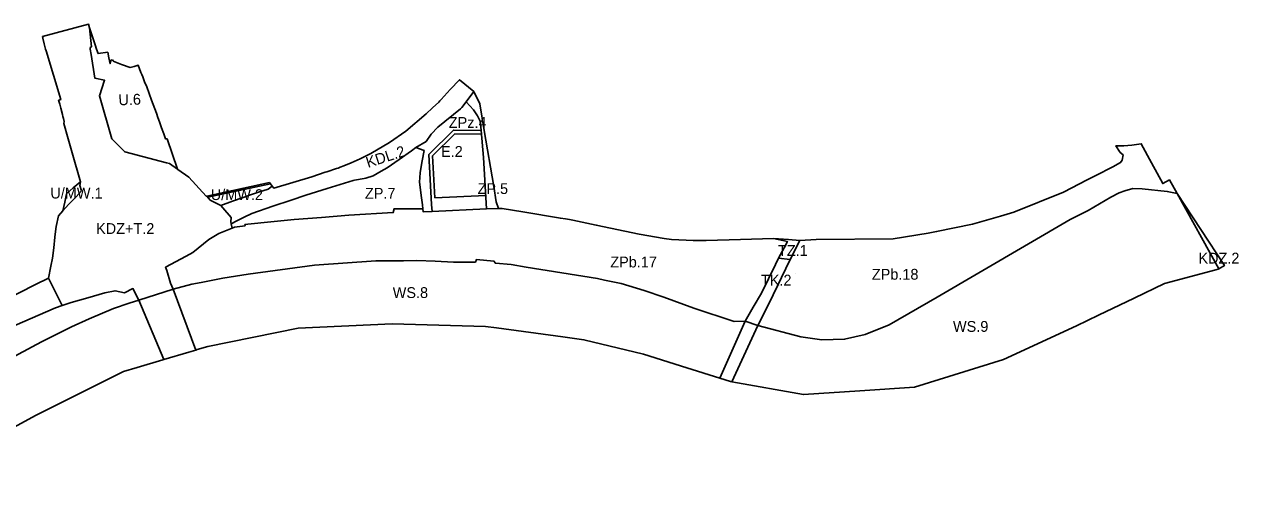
# Model space of a CAD drawing. Extents: x 7421697 to 7426767, y 5545731 to 5547485.
# Drawn here: x 7425420 to 7426767, y 5546623 to 5547146 of the extents above; entities that cross this region are included whole.
import ezdxf

# ---------------------------------------------------------------- set-up
doc = ezdxf.new("R2010")
doc.units = 0
for name, color, linetype in [('LIN_Linia Zabudowy Nieprzekraczalna', 7, 'Continuous'), ('LIN_linie rozgraniczające terenu WS', 7, 'Continuous'), ('LIN_linie_rozgraniczajace', 7, 'Continuous'), ('TXT_oznaczenia_przeznaczen', 7, 'Continuous')]:
    doc.layers.add(name, color=color, linetype=linetype)

msp = doc.modelspace()

# ---------------------------------------------------------------- linework, layer by layer
at = {"layer": 'LIN_Linia Zabudowy Nieprzekraczalna'}
for p, q in [((7425623.5, 5546954.6), (7425693.1, 5546969.4)), ((7425875.5, 5546953.9), (7425931.9, 5546956.6))]:
    msp.add_line(p, q, dxfattribs=at)
for points in [[(7425926.9, 5547024.5), (7425897.7, 5547025.1), (7425872.8, 5547000.4)], [(7425872.8, 5547000.4), (7425875.5, 5546953.9)]]:
    msp.add_lwpolyline(points, dxfattribs=at)
at = {"layer": 'LIN_linie rozgraniczające terenu WS'}
for p, q in [((7425585.1, 5546852.7), (7425547.1, 5546840.6)), ((7426233.8, 5546812.6), (7426219.6, 5546817.2))]:
    msp.add_line(p, q, dxfattribs=at)
at = {"layer": 'LIN_linie_rozgraniczajace'}
for p, q in [((7425929.5, 5546998.7), (7425927, 5547028.5)), ((7425854.4, 5547009.9), (7425863.7, 5547006.3)), ((7425481.8, 5546967.8), (7425482.3, 5546971.6)), ((7426745.1, 5546875.3), (7426698.6, 5546958.8)), ((7426256.7, 5546886.9), (7426269.7, 5546885.5)), ((7425446.8, 5546864.8), (7425462.3, 5546834.6)), ((7425574.9, 5546774.7), (7425547.1, 5546840.6)), ((7426219.6, 5546817.2), (7426191.5, 5546754)), ((7426233.8, 5546812.6), (7426205, 5546749.9))]:
    msp.add_line(p, q, dxfattribs=at)
for points in [[(7425395.5, 5546839), (7425432.7, 5546857.7), (7425446.8, 5546864.8), (7425449.6, 5546878.2), (7425451.5, 5546887.1), (7425452.7, 5546898.6), (7425454, 5546910.5), (7425455, 5546919.7), (7425455.5, 5546922), (7425457.9, 5546933.9), (7425462.7, 5546939.4), (7425464.9, 5546949.3), (7425466.8, 5546958.3), (7425474.5, 5546965), (7425482.3, 5546971.6), (7425473.1, 5547004), (7425468.7, 5547019.4), (7425463.9, 5547036.5), (7425464.4, 5547038.7), (7425463.5, 5547041.9), (7425462.9, 5547044.1), (7425462.4, 5547046.3), (7425460.8, 5547053.4), (7425459.5, 5547057.8), (7425458.2, 5547062.1), (7425459.4, 5547062.5), (7425460.6, 5547062.8), (7425452.4, 5547089.9), (7425444.3, 5547116.9), (7425443.8, 5547118.9), (7425442.3, 5547124.8), (7425440.8, 5547130.8), (7425440.6, 5547131.8), (7425440.3, 5547132.9), (7425491.4, 5547146.4), (7425492.6, 5547142.6), (7425498.8, 5547123.4), (7425500.3, 5547118.8), (7425501.9, 5547113.8), (7425512.7, 5547115.4), (7425514, 5547109.1), (7425515.2, 5547102.7), (7425515.9, 5547104.8), (7425516.6, 5547106.8), (7425519, 5547106.1), (7425518.8, 5547105.5), (7425528, 5547101.6), (7425537.4, 5547098.3), (7425541.9, 5547099.6), (7425546.5, 5547101), (7425548, 5547097), (7425549.5, 5547093), (7425550.4, 5547090.6), (7425551.4, 5547088.2), (7425553.6, 5547082.6), (7425555.9, 5547076.9), (7425561.2, 5547062.4), (7425566.6, 5547047.9), (7425568.2, 5547043.1), (7425569.9, 5547038.4), (7425572.2, 5547031.6), (7425574.7, 5547024.8), (7425576.7, 5547019.4), (7425578.5, 5547019.2), (7425590.1, 5546985.9), (7425590.3, 5546985.2), (7425602.5, 5546977), (7425621.9, 5546955.7), (7425622.4, 5546955.8), (7425691.9, 5546970.8), (7425695.1, 5546966.9), (7425697, 5546964.6), (7425739.2, 5546977.4), (7425753.7, 5546982.3), (7425755.7, 5546982.9), (7425766.3, 5546986.3), (7425768.4, 5546987), (7425770.5, 5546987.8), (7425774.6, 5546989.3), (7425782.7, 5546992.6), (7425792.6, 5546997.2), (7425804.3, 5547003.1), (7425825.1, 5547015.3), (7425843.1, 5547027.9), (7425866, 5547047), (7425872.8, 5547053.6), (7425879.7, 5547060.2), (7425881, 5547061.6), (7425882.3, 5547063), (7425892.5, 5547074), (7425902.8, 5547084.9), (7425918.6, 5547072), (7425925.3, 5547058.1), (7425930.3, 5547028.5), (7425940.7, 5546966.7), (7425943.6, 5546949.5), (7425945.9, 5546942.3), (7425950, 5546942), (7425972.9, 5546938.4), (7426014.8, 5546931.3), (7426020.2, 5546930.6), (7426024.8, 5546929.9), (7426028.5, 5546929.2), (7426054.5, 5546923.8), (7426102.1, 5546913.6), (7426129.8, 5546908.8), (7426138.1, 5546907.8), (7426154.2, 5546907), (7426162.1, 5546906.7), (7426176.2, 5546906.8), (7426214.4, 5546907.8), (7426251.2, 5546908.7), (7426267.7, 5546907.6), (7426280.4, 5546906.8), (7426298.2, 5546907.8), (7426383.7, 5546908.5), (7426422.5, 5546914.8), (7426432, 5546916.5), (7426471.8, 5546924.7), (7426502.7, 5546933.5), (7426517.6, 5546938.1), (7426572.7, 5546960.2), (7426599, 5546973.9), (7426608.7, 5546978.9), (7426627.5, 5546988.4), (7426635.9, 5546993.1), (7426637.6, 5546995.9), (7426638.7, 5547001.5), (7426635.6, 5547004.4), (7426630.8, 5547011.7), (7426636.1, 5547011.6), (7426639.5, 5547011.5), (7426648.5, 5547012.4), (7426658.9, 5547014), (7426670.2, 5546992.7), (7426682.8, 5546969.8), (7426690.1, 5546973.9), (7426698.6, 5546958.8), (7426751.2, 5546878.9), (7426745.1, 5546875.3), (7426744.2, 5546874.7), (7426741.8, 5546874.1), (7426684.8, 5546858.9), (7426651.2, 5546842.7), (7426611.5, 5546823.9), (7426587, 5546812.2), (7426506.2, 5546774.8), (7426407.3, 5546744), (7426346.9, 5546740), (7426284.3, 5546735.8), (7426205, 5546749.9), (7426203.3, 5546750.2), (7426191.5, 5546754), (7426155.1, 5546765.4), (7426106.9, 5546780.6), (7426040.7, 5546796.6), (7426017.4, 5546799.8), (7425943.8, 5546809.7), (7425931.6, 5546811.4), (7425828.1, 5546814.3), (7425724, 5546809.4), (7425623.7, 5546789.1), (7425612, 5546785.7), (7425610.2, 5546785.1), (7425602.7, 5546782.9), (7425574.9, 5546774.7), (7425573.9, 5546774.4), (7425545.3, 5546765.9), (7425530.3, 5546761.5), (7425432.4, 5546712.6), (7425356.2, 5546671.4)], [(7425517.2, 5547019.3), (7425503.4, 5547067.2), (7425509.1, 5547084.3), (7425498.3, 5547086.8), (7425494.3, 5547112.7), (7425493.3, 5547118.8), (7425493.1, 5547120.5), (7425494.8, 5547121.4), (7425492.6, 5547142.6)], [(7425854.4, 5547009.9), (7425865.7, 5547016.6), (7425871.2, 5547024.5), (7425878.6, 5547032.2), (7425903.8, 5547052.8), (7425905.4, 5547054.1), (7425910.1, 5547060.4), (7425918.6, 5547072)], [(7425910.1, 5547060.4), (7425918.5, 5547051.4), (7425922.8, 5547044.8), (7425925.6, 5547039.1), (7425926.6, 5547032.8), (7425927, 5547028.5)], [(7425868.7, 5547002), (7425896.1, 5547029.1), (7425927, 5547028.5)], [(7425590.1, 5546985.9), (7425581, 5546992.1), (7425577.8, 5546992.9), (7425531.5, 5547004.9), (7425517.2, 5547019.3)], [(7425786.3, 5546973.4), (7425797, 5546975.5), (7425798.8, 5546975.9), (7425807.1, 5546978.2), (7425815.9, 5546983.4), (7425822.4, 5546987.2), (7425836, 5546996.6), (7425849.7, 5547006.1), (7425854.4, 5547009.9)], [(7425863.7, 5547006.3), (7425861.5, 5546994.9), (7425859.2, 5546982), (7425858.9, 5546976.2), (7425858.6, 5546971.8), (7425860.4, 5546956.7), (7425861.6, 5546946.1), (7425862.1, 5546941.6)], [(7425868.7, 5547002), (7425871.9, 5546946.5), (7425872.4, 5546938.9)], [(7425929.5, 5546998.7), (7425932.7, 5546941.7)], [(7425649.5, 5546925.3), (7425655.7, 5546928.6), (7425664, 5546932.7), (7425672.6, 5546936.5), (7425695.7, 5546944.6), (7425716.2, 5546951.2), (7425732.5, 5546957), (7425756, 5546964.3), (7425784.9, 5546973.1), (7425786.3, 5546973.4)], [(7425483.4, 5546961.6), (7425477.5, 5546955.2), (7425469, 5546946.6), (7425462.7, 5546939.4)], [(7425481.8, 5546967.8), (7425483.4, 5546961.6)], [(7425638.1, 5546945.3), (7425651.2, 5546950.2), (7425663, 5546954.5), (7425671.1, 5546957.4), (7425678.9, 5546959.7), (7425690.6, 5546963.6), (7425695.1, 5546966.9)], [(7426698.6, 5546958.8), (7426687.7, 5546961), (7426660, 5546964), (7426649.7, 5546964.4), (7426640.6, 5546961.8), (7426634.6, 5546959.4), (7426625.3, 5546954.8), (7426599.9, 5546939.9), (7426579.9, 5546929.8), (7426432.4, 5546844), (7426379.5, 5546813.2), (7426352.7, 5546802.6), (7426329.8, 5546797.1), (7426304.6, 5546796.6), (7426281.4, 5546799.7), (7426233.8, 5546812.6)], [(7425578.3, 5546873.5), (7425577.5, 5546875.4), (7425576.8, 5546877), (7425599.5, 5546889.2), (7425607, 5546893.3), (7425624.8, 5546907.6), (7425635.8, 5546914.6), (7425650.6, 5546920.4), (7425649.5, 5546925.3), (7425649.1, 5546927.3), (7425649.6, 5546932.1), (7425640.2, 5546942.9), (7425638.1, 5546945.3), (7425626.3, 5546951.5), (7425622.4, 5546955.8)], [(7425862.1, 5546941.6), (7425858.4, 5546941.7), (7425844.4, 5546941.7), (7425830.3, 5546941.8), (7425829.4, 5546937.6), (7425780.2, 5546934.7), (7425749.8, 5546932.2), (7425719.4, 5546929.8), (7425693.6, 5546927.2), (7425667.9, 5546924.7), (7425664.8, 5546924.4)], [(7425862.1, 5546941.6), (7425862.5, 5546938.4), (7425872.4, 5546938.9), (7425932.7, 5546941.7), (7425945.9, 5546942.3)], [(7425650.6, 5546920.4), (7425653.2, 5546921.5), (7425665, 5546923.1), (7425664.8, 5546924.4)], [(7426219.6, 5546817.2), (7426228.6, 5546832.8), (7426237.6, 5546848.3), (7426245.4, 5546864.2), (7426253.2, 5546880.1), (7426256.7, 5546886.9), (7426258.9, 5546891.2), (7426262.7, 5546898.4), (7426266.4, 5546905.7), (7426251.2, 5546908.7)], [(7426233.8, 5546812.6), (7426245.9, 5546836.6), (7426269.7, 5546885.5), (7426280.4, 5546906.8)], [(7426219.6, 5546817.2), (7426207.4, 5546816.7), (7426162.6, 5546831.5), (7426129.6, 5546843.7), (7426107.6, 5546851.4), (7426082.1, 5546858.9), (7426063.7, 5546862.8), (7426055.9, 5546864.5), (7425976.6, 5546877.2), (7425960, 5546879.9), (7425942.6, 5546881.4), (7425940.9, 5546883.8), (7425921.5, 5546885.5), (7425920.5, 5546882.8), (7425896.3, 5546882.8), (7425875.9, 5546883.6), (7425855.6, 5546884.5), (7425840.5, 5546884), (7425809.9, 5546884), (7425741.9, 5546879.5), (7425668.4, 5546869.4), (7425640.4, 5546864.9), (7425616.3, 5546860.2), (7425605.8, 5546858.1), (7425585.1, 5546852.7)], [(7425610.2, 5546785.1), (7425585.1, 5546852.7), (7425582.4, 5546859.5), (7425578.3, 5546873.5)], [(7425150.3, 5546640.5), (7425174.7, 5546675.6), (7425209.1, 5546707.5), (7425225.2, 5546719.1), (7425256.8, 5546736.4), (7425320.6, 5546768), (7425366.2, 5546790.8), (7425409.8, 5546812.5), (7425454.9, 5546831.9), (7425462.3, 5546834.6), (7425472.1, 5546838.1), (7425490.6, 5546843), (7425509.4, 5546848.5), (7425520.8, 5546850.9), (7425531.3, 5546848.5)], [(7425531.3, 5546848.5), (7425540.5, 5546853.3), (7425547.1, 5546840.6)], [(7425168.8, 5546622.6), (7425179.2, 5546631.5), (7425195.5, 5546644.6), (7425212.7, 5546658.1), (7425211.5, 5546659.7), (7425231.2, 5546674.1), (7425232.3, 5546672.5), (7425246.5, 5546682.6), (7425265.8, 5546695.5), (7425281.9, 5546705.9), (7425297.6, 5546715.5), (7425301, 5546717.6), (7425312.7, 5546724.3), (7425324.3, 5546731.1), (7425413.8, 5546780.7), (7425439.3, 5546794.4), (7425453.1, 5546801.4), (7425472.4, 5546810.9), (7425492.1, 5546819.9), (7425518.9, 5546831.1), (7425536.4, 5546837.3), (7425547.1, 5546840.6)]]:
    msp.add_lwpolyline(points, dxfattribs=at)
at = {"layer": 'TXT_oznaczenia_przeznaczen'}
msp.add_line((7426275.7, 5546870.6), (7426275.7, 5546870.6), dxfattribs=at)

# ---------------------------------------------------------------- texts
for s, rotation, p in [('U.6', 1.9636, (7425524.7, 5547056.5)), ('KDL.2', 17.7764, (7425801.3, 5546987.1))]:
    msp.add_text(s, height=12, rotation=rotation, dxfattribs=at).set_placement(p)
for s, p in [('ZPz.4', (7425890.9, 5547031.5)), ('E.2', (7425882.3, 5546999.4)), ('ZP.5', (7425922.8, 5546958.2)), ('U/MW.1', (7425449, 5546953.2)), ('U/MW.2', (7425626.9, 5546951.5)), ('ZP.7', (7425797.9, 5546953)), ('KDZ+T.2', (7425499.7, 5546913.9)), ('ZPb.17', (7426070, 5546876.8)), ('TZ.1', (7426256, 5546889.6)), ('KDZ.2', (7426722.3, 5546881.1)), ('ZPb.18', (7426360.1, 5546863.2)), ('TK.2', (7426237.1, 5546856.7)), ('WS.8', (7425828.7, 5546842.9)), ('WS.9', (7426450.1, 5546805.4))]:
    msp.add_text(s, height=12, dxfattribs=at).set_placement(p)

doc.saveas('drawing.dxf')
